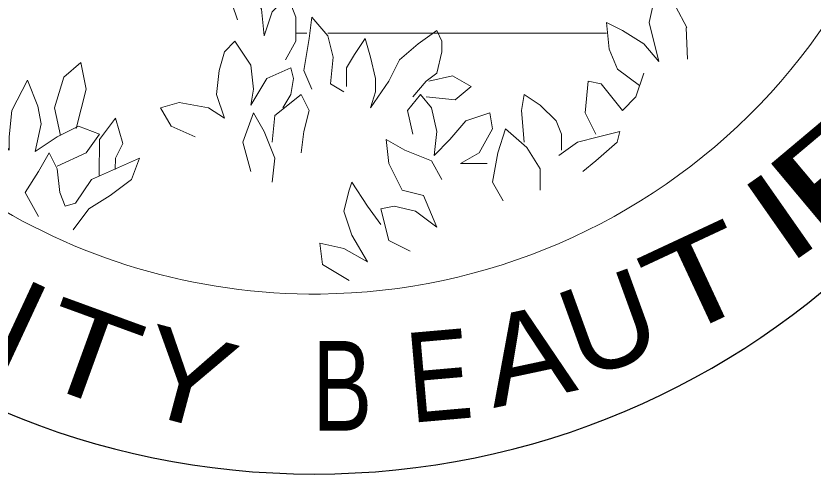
# Model space of a CAD drawing. Extents: x 44.6 to 61.6, y -38.7 to -27.7.
# Drawn here: x 46.2588 to 46.6452, y -37.8841 to -37.6622 of the extents above; entities that cross this region are included whole.
import ezdxf
from ezdxf.enums import TextEntityAlignment as Align

# ---------------------------------------------------------------- set-up
doc = ezdxf.new("R2010")
doc.units = 0
doc.header["$LTSCALE"] = 0.025
doc.layers.add('60', color=7, linetype='Continuous', lineweight=13)

msp = doc.modelspace()

# ---------------------------------------------------------------- linework, layer by layer
at = {"layer": '60'}
for p, q in [((46.39972, -37.67059), (46.39454, -37.67059)), ((46.40998, -37.67059), (46.54512, -37.67059))]:
    msp.add_line(p, q, dxfattribs=at)
for points in [[(46.36625, -37.66416), (46.36364, -37.65644), (46.37003, -37.64482), (46.37266, -37.64998), (46.37781, -37.65899), (46.37908, -37.67189), (46.38299, -37.66031), (46.39065, -37.65258), (46.39454, -37.66286), (46.39454, -37.67447), (46.3894, -37.68345)], [(46.56103, -37.69591), (46.55049, -37.68799), (46.54637, -37.67832), (46.54512, -37.66542), (46.55288, -37.66931), (46.56314, -37.67577), (46.57047, -37.68436), (46.56572, -37.66542), (46.56964, -37.64783), (46.57865, -37.65782), (46.58398, -37.66778), (46.58375, -37.66804), (46.58431, -37.68311)], [(46.40223, -37.6976), (46.3984, -37.68863), (46.401, -37.67315), (46.40223, -37.66286), (46.40998, -37.67189), (46.41255, -37.68222), (46.41126, -37.69507), (46.41769, -37.69891)], [(46.41901, -37.69635), (46.41901, -37.68734), (46.42286, -37.6809), (46.42801, -37.67315), (46.43059, -37.68222), (46.43315, -37.69248), (46.43315, -37.69891), (46.43059, -37.70664), (46.43961, -37.69378), (46.44475, -37.68345), (46.45378, -37.67577), (46.46278, -37.66931), (46.46533, -37.67447), (46.46533, -37.67959), (46.46278, -37.6899), (46.45758, -37.69378), (46.4512, -37.70146)], [(46.34559, -37.72079), (46.33401, -37.71561), (46.32889, -37.70664), (46.33792, -37.70406), (46.35207, -37.70664), (46.3598, -37.71176), (46.35593, -37.70025), (46.35723, -37.68863), (46.3598, -37.67959), (46.36493, -37.67447), (46.37266, -37.68607), (46.37396, -37.6976), (46.37266, -37.70535), (46.38039, -37.69248), (46.39197, -37.68734), (46.39325, -37.69248), (46.39197, -37.70025), (46.38811, -37.70664)], [(46.28031, -37.72018), (46.27744, -37.70664), (46.28202, -37.69194), (46.29027, -37.68477), (46.29284, -37.6976), (46.28797, -37.71675)], [(46.53993, -37.71951), (46.53482, -37.70921), (46.53615, -37.69378), (46.54255, -37.69507), (46.55288, -37.70794), (46.55928, -37.70146), (46.56314, -37.6899)], [(46.24394, -37.7362), (46.23751, -37.72462), (46.23751, -37.70664), (46.24524, -37.71441), (46.25554, -37.72722), (46.25554, -37.72079), (46.25682, -37.70794), (46.26431, -37.69335), (46.26942, -37.70591), (46.271, -37.71441), (46.26812, -37.72789), (46.27869, -37.72079), (46.28901, -37.71561), (46.29927, -37.71951), (46.29284, -37.72854), (46.27869, -37.73497)], [(46.45891, -37.69378), (46.47049, -37.69118), (46.47949, -37.69635), (46.47178, -37.7028), (46.45758, -37.70146)], [(46.38299, -37.7234), (46.38422, -37.71051), (46.39712, -37.70025), (46.401, -37.70794), (46.3984, -37.71819), (46.39712, -37.72854)], [(46.4512, -37.71951), (46.4486, -37.70794), (46.45498, -37.70025), (46.46018, -37.70664), (46.46278, -37.71819), (46.46148, -37.72977), (46.46914, -37.72209), (46.47692, -37.71306), (46.4885, -37.70921), (46.48979, -37.71696), (46.48334, -37.72854), (46.47434, -37.73365), (46.48718, -37.73365)], [(46.50523, -37.7234), (46.50396, -37.70794), (46.50523, -37.70025), (46.51296, -37.70535), (46.52069, -37.71306), (46.52326, -37.71951), (46.52326, -37.72722)], [(46.37266, -37.73755), (46.36883, -37.7234), (46.37396, -37.70921), (46.37908, -37.71819), (46.38422, -37.73109), (46.38299, -37.74264)], [(46.29903, -37.73944), (46.29927, -37.72209), (46.30705, -37.71176), (46.31061, -37.72401), (46.30705, -37.73109), (46.30679, -37.73655)], [(46.49493, -37.75171), (46.48979, -37.74264), (46.49237, -37.72854), (46.4962, -37.71696), (46.50653, -37.72597), (46.51296, -37.7362), (46.51296, -37.74653)], [(46.52197, -37.72977), (46.53097, -37.7234), (46.54127, -37.72079), (46.55155, -37.71819), (46.55028, -37.7234), (46.53993, -37.73235), (46.53354, -37.73755)], [(46.44987, -37.77615), (46.43961, -37.77099), (46.43574, -37.75556), (46.44217, -37.75426), (46.45243, -37.75683), (46.46278, -37.76452), (46.45633, -37.7491), (46.44602, -37.74653), (46.43961, -37.73365), (46.43829, -37.72209), (46.44732, -37.72722), (46.46018, -37.73235), (46.46533, -37.74137)], [(46.26971, -37.75942), (46.2633, -37.7478), (46.26971, -37.73755), (46.27485, -37.72854), (46.27869, -37.7362), (46.27999, -37.7478), (46.28258, -37.75426), (46.28769, -37.75294), (46.29544, -37.74137), (46.30705, -37.7362), (46.3186, -37.73109), (46.31478, -37.74137), (46.30443, -37.7491), (46.29415, -37.75556), (46.28644, -37.76584)], [(46.42028, -37.7903), (46.40743, -37.78255), (46.40612, -37.77227), (46.41769, -37.77482), (46.42929, -37.7813), (46.42158, -37.7684), (46.41769, -37.75683), (46.42028, -37.74653), (46.42158, -37.74264), (46.42929, -37.75426), (46.43574, -37.76326)]]:
    msp.add_lwpolyline(points, dxfattribs=at)
for start, end in [(359.20516, 270.606), (270.60601, 1.49336)]:
    msp.add_arc((46.40331, -37.49665), 0.30024, start, end, dxfattribs=at)
at = {"layer": '60', "lineweight": 25}
msp.add_arc((46.40331, -37.49665), 0.387407, 180, 0, dxfattribs=at)

# ---------------------------------------------------------------- texts
at = {"layer": '60'}
for s, rotation, width, p in [('F', 40, 1.8, (46.67075, -37.752)), ('I', 35, 1.5, (46.64165, -37.77715)), ('T', 25, 1.4, (46.59899, -37.80948)), ('U', 20, 1.05, (46.55371, -37.83134)), ('I', 335, 1.15, (46.25165, -37.83169)), ('T', 340, 1.3, (46.28696, -37.84637)), ('A', 12, 1.1, (46.51104, -37.84771)), ('Y', 345, 1.15, (46.33604, -37.85865)), ('E', 5, 0.8, (46.46578, -37.85795))]:
    msp.add_text(s, height=0.04347, rotation=rotation, dxfattribs=dict(at, width=width)).set_placement(p, align=Align.CENTER)
at = {"layer": '60', "width": 0.75}
msp.add_text('B', height=0.04347, dxfattribs=at).set_placement((46.41698, -37.86305), align=Align.CENTER)

doc.saveas('drawing.dxf')
